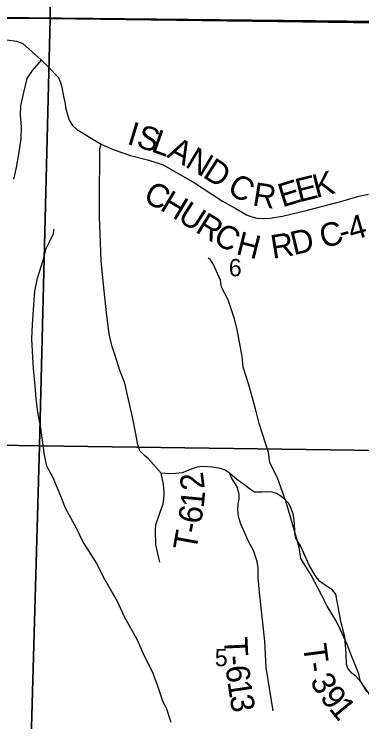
# Model space of a CAD drawing. Extents: x 2.1 to 8.9, y 14.1 to 20.9.
# Drawn here: x 5.459 to 6.298, y 17.436 to 19.144 of the extents above; entities that cross this region are included whole.
import ezdxf

# ---------------------------------------------------------------- set-up
doc = ezdxf.new("R2010")
doc.units = 0
for name, color, linetype in [('Default', 7, 'Continuous'), ('GM_X_City_Street', 7, 'Continuous'), ('GM_X_County_Road_Text', 7, 'Continuous'), ('GM_X_Interchange_Ramps', 7, 'Continuous'), ('GM_X_Minor_River', 7, 'Continuous'), ('GM_X_Minor_River_Text', 7, 'Continuous'), ('GM_X_State_Shield', 7, 'Continuous'), ('TX_P_Misc', 7, 'Continuous')]:
    doc.layers.add(name, color=color, linetype=linetype)

msp = doc.modelspace()

# ---------------------------------------------------------------- linework, layer by layer
at = {"layer": 'Default'}
for p, q in [((6.8944, 19.1204), (5.4005, 19.1369)), ((5.4005, 19.1369), (6.8944, 19.1204))]:
    msp.add_line(p, q, dxfattribs=at)
at = {"layer": 'GM_X_City_Street'}
for p, q in [((5.5029, 19.0083), (5.5245, 19.0331)), ((5.49, 18.9894), (5.5029, 19.0083)), ((5.4824, 18.9556), (5.49, 18.9894)), ((5.4751, 18.9231), (5.4824, 18.9556)), ((5.4744, 18.9024), (5.4751, 18.9231)), ((5.4766, 18.8716), (5.4744, 18.9024)), ((5.4759, 18.844), (5.4766, 18.8716)), ((5.4702, 18.8062), (5.4759, 18.844)), ((5.6657, 18.8193), (5.6689, 18.8303)), ((5.6658, 18.7868), (5.6657, 18.8193)), ((5.4649, 18.7745), (5.4702, 18.8062)), ((5.6648, 18.7226), (5.6658, 18.7868)), ((5.458, 18.7457), (5.4649, 18.7745)), ((5.6645, 18.6544), (5.6648, 18.7226)), ((5.6665, 18.6139), (5.6645, 18.6544)), ((5.6691, 18.549), (5.6665, 18.6139)), ((5.6751, 18.4834), (5.6691, 18.549)), ((5.6828, 18.4169), (5.6751, 18.4834)), ((5.688, 18.3726), (5.6828, 18.4169)), ((5.6945, 18.3445), (5.688, 18.3726)), ((5.7029, 18.3203), (5.6945, 18.3445)), ((5.7138, 18.2837), (5.7029, 18.3203)), ((5.7263, 18.2531), (5.7138, 18.2837)), ((5.7361, 18.2064), (5.7263, 18.2531)), ((5.7442, 18.172), (5.7361, 18.2064)), ((5.7523, 18.1311), (5.7442, 18.172)), ((5.7575, 18.1043), (5.7523, 18.1311)), ((5.7623, 18.0902), (5.7575, 18.1043)), ((5.7731, 18.0787), (5.7623, 18.0902)), ((5.7831, 18.0709), (5.7731, 18.0787)), ((5.8138, 18.0363), (5.7831, 18.0709)), ((5.8879, 18.0462), (5.8749, 18.0407)), ((5.8888, 18.0466), (5.8879, 18.0462)), ((5.9003, 18.0508), (5.8888, 18.0466)), ((5.9134, 18.0521), (5.9003, 18.0508)), ((5.9367, 18.0503), (5.9134, 18.0521)), ((5.9559, 18.0472), (5.9367, 18.0503)), ((5.9682, 18.0431), (5.9559, 18.0472)), ((5.8338, 18.0343), (5.8138, 18.0363)), ((5.8168, 18.0208), (5.8138, 18.0363)), ((5.8489, 18.0354), (5.8338, 18.0343)), ((5.8642, 18.0372), (5.8489, 18.0354)), ((5.8749, 18.0407), (5.8642, 18.0372)), ((5.9783, 18.0364), (5.9682, 18.0431)), ((5.9966, 18.0208), (5.9783, 18.0364)), ((5.9845, 18.0231), (5.9783, 18.0364)), ((5.8189, 18.0092), (5.8168, 18.0208)), ((5.9902, 18.0139), (5.9845, 18.0231)), ((5.9978, 18.0018), (5.9902, 18.0139)), ((6.0157, 18.007), (5.9966, 18.0208)), ((5.8209, 17.9903), (5.8189, 18.0092)), ((6.0019, 17.9847), (5.9978, 18.0018)), ((6.0265, 17.998), (6.0157, 18.007)), ((6.0386, 17.9903), (6.0265, 17.998)), ((5.8187, 17.9621), (5.8212, 17.9824)), ((5.8212, 17.9824), (5.8209, 17.9903)), ((6.0019, 17.9742), (6.0019, 17.9847)), ((6.0562, 17.9901), (6.0386, 17.9903)), ((6.0675, 17.9914), (6.0562, 17.9901)), ((6.0813, 17.9904), (6.0675, 17.9914)), ((6.0918, 17.9872), (6.0813, 17.9904)), ((6.1023, 17.9808), (6.0918, 17.9872)), ((6.1122, 17.9727), (6.1023, 17.9808)), ((5.8073, 17.9309), (5.8187, 17.9621)), ((5.9986, 17.9476), (5.9993, 17.9611)), ((5.9993, 17.9611), (6.0019, 17.9742)), ((6.1209, 17.9634), (6.1122, 17.9727)), ((6.1261, 17.9547), (6.1209, 17.9634)), ((6.0002, 17.9315), (5.9986, 17.9476)), ((6.1325, 17.9378), (6.1261, 17.9547)), ((5.8007, 17.9112), (5.8073, 17.9309)), ((6.006, 17.913), (6.0002, 17.9315)), ((6.1346, 17.9243), (6.1325, 17.9378)), ((5.7997, 17.8987), (5.8007, 17.9112)), ((6.0157, 17.891), (6.006, 17.913)), ((6.1358, 17.8974), (6.1346, 17.9243)), ((5.8009, 17.8633), (5.7997, 17.8987)), ((6.1369, 17.8874), (6.1358, 17.8974)), ((6.0245, 17.8707), (6.0157, 17.891)), ((6.1389, 17.8795), (6.1369, 17.8874)), ((6.1502, 17.8605), (6.1389, 17.8795)), ((5.8107, 17.8213), (5.8009, 17.8633)), ((6.0363, 17.8493), (6.0245, 17.8707)), ((6.1576, 17.8428), (6.1502, 17.8605)), ((6.0455, 17.8224), (6.0363, 17.8493)), ((6.1707, 17.8139), (6.1576, 17.8428)), ((6.0478, 17.8076), (6.0455, 17.8224)), ((6.048, 17.7838), (6.0478, 17.8076)), ((6.1849, 17.7891), (6.1707, 17.8139)), ((6.0506, 17.7477), (6.048, 17.7838)), ((6.1963, 17.7743), (6.1849, 17.7891)), ((6.2091, 17.7658), (6.1963, 17.7743)), ((6.2265, 17.7543), (6.2091, 17.7658)), ((6.0641, 17.6302), (6.0506, 17.7477)), ((6.2347, 17.7435), (6.2265, 17.7543)), ((6.241, 17.7143), (6.2347, 17.7435)), ((6.2469, 17.6778), (6.241, 17.7143)), ((6.2567, 17.6411), (6.2469, 17.6778)), ((6.26, 17.6), (6.2567, 17.6411)), ((6.067, 17.5666), (6.0641, 17.6302)), ((6.2607, 17.5741), (6.26, 17.6)), ((6.2649, 17.5633), (6.2607, 17.5741)), ((6.0838, 17.4625), (6.067, 17.5666)), ((6.2738, 17.5528), (6.2649, 17.5633)), ((6.2837, 17.5459), (6.2738, 17.5528)), ((6.2953, 17.5319), (6.2837, 17.5459)), ((6.296, 17.5311), (6.2953, 17.5319)), ((6.3276, 17.4852), (6.296, 17.5311))]:
    msp.add_line(p, q, dxfattribs=at)
at = {"layer": 'GM_X_Interchange_Ramps'}
for p, q in [((5.5505, 20.1287), (5.5458, 19.1336)), ((5.5458, 19.1336), (5.5505, 20.1287)), ((5.5458, 19.1336), (4.5388, 19.1444)), ((4.5388, 19.1444), (5.5458, 19.1336)), ((5.5458, 19.1336), (5.5198, 18.1024)), ((5.5198, 18.1024), (5.5458, 19.1336)), ((6.4599, 19.1223), (5.5458, 19.1336)), ((5.5458, 19.1336), (6.4599, 19.1223)), ((5.5198, 18.1024), (4.5166, 18.1148)), ((4.5166, 18.1148), (5.5198, 18.1024)), ((5.5198, 18.1024), (5.492, 17.1117)), ((5.492, 17.1117), (5.5198, 18.1024)), ((6.4465, 18.0895), (5.5198, 18.1024)), ((5.5198, 18.1024), (6.4465, 18.0895))]:
    msp.add_line(p, q, dxfattribs=at)
at = {"layer": 'GM_X_State_Shield'}
for p, q in [((5.441, 19.0825), (5.4647, 19.0796)), ((5.4647, 19.0796), (5.4794, 19.0736)), ((5.4794, 19.0736), (5.5245, 19.0331)), ((5.5245, 19.0331), (5.54, 19.0182)), ((5.54, 19.0182), (5.5659, 18.9914)), ((5.5659, 18.9914), (5.5709, 18.9798)), ((5.5709, 18.9798), (5.5742, 18.9685)), ((5.5742, 18.9685), (5.5783, 18.9456)), ((5.5783, 18.9456), (5.5815, 18.9316)), ((5.5815, 18.9316), (5.5838, 18.9157)), ((5.5838, 18.9157), (5.5868, 18.9047)), ((5.5868, 18.9047), (5.5914, 18.8886)), ((5.5914, 18.8886), (5.5998, 18.8757)), ((5.5998, 18.8757), (5.61, 18.8661)), ((5.61, 18.8661), (5.6689, 18.8303)), ((5.6689, 18.8303), (5.6981, 18.8179)), ((5.6981, 18.8179), (5.7396, 18.8033)), ((5.7396, 18.8033), (5.7841, 18.7919)), ((5.7841, 18.7919), (5.8182, 18.7806)), ((5.8182, 18.7806), (5.8938, 18.7375)), ((5.8938, 18.7375), (5.9614, 18.6931)), ((6.2524, 18.6936), (6.2907, 18.7051)), ((6.2907, 18.7051), (6.314, 18.7099)), ((5.9614, 18.6931), (5.9919, 18.6759)), ((6.1701, 18.6717), (6.2524, 18.6936)), ((5.9919, 18.6759), (6.0071, 18.6668)), ((6.0071, 18.6668), (6.0197, 18.6602)), ((6.1068, 18.6567), (6.1701, 18.6717)), ((6.0197, 18.6602), (6.03, 18.6559)), ((6.03, 18.6559), (6.0445, 18.6521)), ((6.0445, 18.6521), (6.0591, 18.6509)), ((6.0591, 18.6509), (6.0601, 18.6509)), ((6.0601, 18.6509), (6.0767, 18.6517)), ((6.0767, 18.6517), (6.1068, 18.6567))]:
    msp.add_line(p, q, dxfattribs=at)
at = {"layer": 'TX_P_Misc'}
for p, q in [((5.5444, 18.5945), (5.5539, 18.6148)), ((5.5539, 18.6148), (5.5542, 18.6205)), ((5.5542, 18.6205), (5.5548, 18.6254)), ((5.5364, 18.5784), (5.5444, 18.5945)), ((5.5296, 18.5532), (5.5364, 18.5784)), ((5.5149, 18.5073), (5.5296, 18.5532)), ((5.933, 18.5511), (5.9273, 18.5549)), ((5.9393, 18.5414), (5.933, 18.5511)), ((5.9566, 18.5021), (5.9393, 18.5414)), ((5.5091, 18.4753), (5.5149, 18.5073)), ((5.9592, 18.485), (5.9566, 18.5021)), ((5.5044, 18.42), (5.5091, 18.4753)), ((5.9756, 18.4549), (5.9592, 18.485)), ((5.9899, 18.4114), (5.9756, 18.4549)), ((5.5029, 18.3953), (5.5044, 18.42)), ((5.9969, 18.383), (5.9899, 18.4114)), ((5.5013, 18.3607), (5.5029, 18.3953)), ((6.0093, 18.3178), (5.9969, 18.383)), ((5.5036, 18.3158), (5.5013, 18.3607)), ((5.5059, 18.2892), (5.5036, 18.3158)), ((6.0113, 18.292), (6.0093, 18.3178)), ((5.5097, 18.2471), (5.5059, 18.2892)), ((6.0249, 18.2492), (6.0113, 18.292)), ((5.5117, 18.2159), (5.5097, 18.2471)), ((6.0414, 18.1917), (6.0249, 18.2492)), ((5.5161, 18.1833), (5.5117, 18.2159)), ((5.5235, 18.1454), (5.5161, 18.1833)), ((6.0503, 18.1561), (6.0414, 18.1917)), ((6.0724, 18.0861), (6.0503, 18.1561)), ((5.5262, 18.1218), (5.5235, 18.1454)), ((5.5319, 18.0801), (5.5262, 18.1218)), ((6.0762, 18.0618), (6.0724, 18.0861)), ((5.538, 18.0528), (5.5319, 18.0801)), ((5.5529, 18.0245), (5.538, 18.0528)), ((6.0954, 18.0222), (6.0762, 18.0618)), ((5.5714, 17.9807), (5.5529, 18.0245)), ((6.1148, 17.9681), (6.0954, 18.0222)), ((5.5828, 17.9516), (5.5714, 17.9807)), ((6.1249, 17.9333), (6.1148, 17.9681)), ((5.6094, 17.9033), (5.5828, 17.9516)), ((6.1466, 17.8571), (6.1249, 17.9333)), ((5.6243, 17.8713), (5.6094, 17.9033)), ((5.6573, 17.8197), (5.6243, 17.8713)), ((6.1505, 17.8302), (6.1466, 17.8571)), ((6.1758, 17.7895), (6.1505, 17.8302)), ((5.6742, 17.7849), (5.6573, 17.8197)), ((5.7081, 17.7258), (5.6742, 17.7849)), ((6.2015, 17.7408), (6.1758, 17.7895)), ((6.2141, 17.7152), (6.2015, 17.7408)), ((5.7253, 17.6891), (5.7081, 17.7258)), ((6.2366, 17.6782), (6.2141, 17.7152)), ((5.7565, 17.6329), (5.7253, 17.6891)), ((6.2464, 17.6578), (6.2366, 17.6782)), ((6.2625, 17.6227), (6.2464, 17.6578)), ((5.7707, 17.5997), (5.7565, 17.6329)), ((6.2712, 17.5989), (6.2625, 17.6227)), ((5.7946, 17.5521), (5.7707, 17.5997)), ((6.2906, 17.5516), (6.2712, 17.5989)), ((5.8045, 17.5245), (5.7946, 17.5521)), ((6.2939, 17.5357), (6.2906, 17.5516)), ((6.3102, 17.5085), (6.2939, 17.5357)), ((5.8181, 17.4832), (5.8045, 17.5245)), ((5.8263, 17.4689), (5.8181, 17.4832)), ((5.8374, 17.434), (5.8263, 17.4689))]:
    msp.add_line(p, q, dxfattribs=at)

# ---------------------------------------------------------------- texts
at = {"layer": 'GM_X_County_Road_Text'}
for s, p in [('6', (5.9767, 18.5115)), ('5', (5.943, 17.5699))]:
    msp.add_text(s, height=0.0419, rotation=0, dxfattribs=at).set_placement(p)
at = {"layer": 'GM_X_Minor_River'}
for s, rotation, p in [('I', 343.0488, (5.7288, 18.8316)), ('S', 342.943, (5.7511, 18.8249)), ('L', 340.2937, (5.7871, 18.8138)), ('A', 332.5406, (5.8253, 18.8003)), ('N', 329.3342, (5.8689, 18.7777)), ('D', 327.3223, (5.9115, 18.7524)), ('K', 14.3486, (6.1874, 18.7002)), ('C', 328.9875, (5.9698, 18.7151)), ('E', 14.109, (6.146, 18.6898)), ('C', 332.4365, (5.7675, 18.6941)), ('R', 350.8581, (6.0319, 18.683)), ('E', 17.0747, (6.1061, 18.6775)), ('H', 329.2412, (5.8081, 18.6729)), ('U', 327.2718, (5.8506, 18.6476)), ('R', 328.3994, (5.8937, 18.6199)), ('4', 16.2246, (6.2735, 18.5971)), ('C', 331.1375, (5.936, 18.594)), ('C', 14.6752, (6.2042, 18.5788)), ('H', 345.9077, (5.9918, 18.5656)), ('R', 9.1363, (6.0827, 18.5537)), ('D', 13.6584, (6.1335, 18.562)), ('-', 14.95, (6.2496, 18.5907))]:
    msp.add_text(s, height=0.0568, rotation=rotation, dxfattribs=at).set_placement(p)
at = {"layer": 'GM_X_Minor_River_Text'}
for s, rotation, p in [('2', 97.2326, (5.9192, 17.999)), ('1', 84.4694, (5.9161, 17.9504)), ('6', 80.282, (5.9095, 17.9114)), ('-', 79.9745, (5.9054, 17.8881)), ('T', 79.9155, (5.898, 17.8462)), ('T', 272.731, (5.9649, 17.6392)), ('T', 277.4046, (6.1556, 17.621)), ('-', 274.4328, (5.967, 17.5949)), ('6', 276.5878, (5.969, 17.5693)), ('-', 279.355, (6.1613, 17.5768)), ('3', 298.1775, (6.1716, 17.5346)), ('1', 278.469, (5.9733, 17.5325)), ('9', 309.1408, (6.1947, 17.4939)), ('3', 279.4788, (5.9786, 17.4968)), ('1', 309.1506, (6.2168, 17.4668))]:
    msp.add_text(s, height=0.0568, rotation=rotation, dxfattribs=at).set_placement(p)

doc.saveas('drawing.dxf')
